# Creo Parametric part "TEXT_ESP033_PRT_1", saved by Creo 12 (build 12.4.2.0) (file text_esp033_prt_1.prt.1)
Units: Custom; MM, KILOGRAM, SECS

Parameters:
  PTC_WM_ITERATION = "0"
  PTC_WM_VERSION = "-.0"
  PTC_WM_LIFECYCLE_STATE = "In Work"
  PTC_WM_LIFECYCLE = "MO_CADDocument"
  PTC_WM_CREATED_BY = "Maximilian Roepper (Z0017RMS: MO)"
  PTC_WM_CREATED_ON = "18-Sep-26 11:36:42 AM"
  PTC_WM_MODIFIED_BY = "Maximilian Roepper (Z0017RMS: MO)"
  PTC_WM_MODIFIED_ON = "18-Sep-26 11:36:46 AM"
  PDMLINKNUMBER = "PDM000071454934"
  PTC_WM_NAME = "text_esp033_prt_1.prt"
  PTC_WM_NUMBER = "PDM000071454934"

Other parameters: WEIGHT, WEIGHT_FACTOR, WEIGHT_ADD, _MASS_TEMP, _DIFF_TEMP, MC_ERRORS, SUPPLIER

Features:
  1. coordinate system
  2. datum plane "PRT_YZ"
  3. datum plane "PRT_XY"
  4. datum plane "PRT_XZ"
  5. coordinate system
  6. datum axis
  7. datum axis
  8. datum axis
  9. coordinate system
  10. imported feature
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
Other named items: PRT, SIEMENS_MO, DRW_VIEW_ORG, PRT_X, PRT_Y, PRT_Z, CS0, ROUGH_GROB

Layers: 00_STD_CSYS-KSYS, 01_STD_PLANES-EBENEN, 02_STD_AXES-ACHSEN, 03_STD_CSYS-KSYS, 24_IMPORT_FEAT-IMPORT_KE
